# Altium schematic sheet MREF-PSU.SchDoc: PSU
size A4; CompanyName: TRINAMIC; DocumentNumber: 3; SheetNumber: 3; SheetTotal: 5; Author: Indrek Rebane; DrawnBy: Indrek Rebane; Engineer: Indrek Rebane; Organization: Hedgehog OÜ; Address1: Waterloohain 5; Address2: 22769 Hamburg; Address3: Germany; Address4: tmc_info@trinamic.com
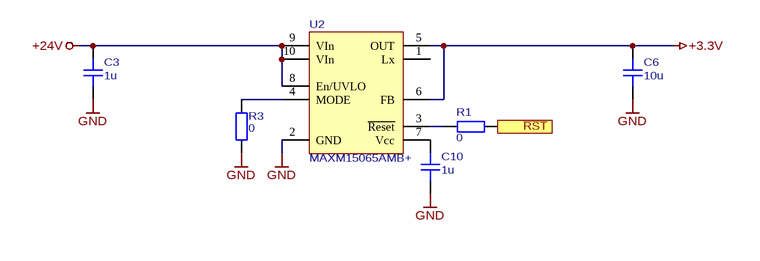
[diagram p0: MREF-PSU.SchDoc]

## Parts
C3  value 1u  [CAPC2012N]  (hidden comment: CAPC)
C6  value 10u  [CAPC2012N]  (hidden comment: CAPC)
C10  value 1u  [CAPC1608N]  (hidden comment: CAPC)
R1  value 0  [RESC1005N]  (hidden comment: RESC)
R3  value 0  [RESC1005N]  (hidden comment: RESC)
U2  Part Number: MAXM15065AMB+  [PSON50P260X165-10N-MFG]  (hidden comment: MAXM1506X)

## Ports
~{RST} (out)

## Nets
+3.3V: C6.2 U2.5(OUT) U2.6(FB)
+24V: C3.2 U2.8(En/UVLO) U2.9(VIn) U2.10(VIn)
GND: C3.1 C6.1 C10.1 R3.2 U2.2(GND)
~{RST}: R1.1 ; port ~{RST}
NetC10_2: C10.2 U2.7(Vcc)
NetR1_2: R1.2 U2.3(~{Reset})
NetR3_1: R3.1 U2.4(MODE)

Not connected (* = marked no-connect by the designer): U2 1(Lx)

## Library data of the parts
C3 = 20079: Ceramic chip capacitor; Manufacturer: Any; Part Number: 1u, 50V, X5R, 0805 (2012 metric) chip capacitor; Id: 20079; Voltage: 50V
C6 = 20166: Ceramic chip capacitor; Manufacturer: Any; Part Number: 10u, 10V, X7R, 0805 (2012 metric) chip capacitor; Id: 20166; Voltage: 10V
C10 = 20005: Ceramic chip capacitor; Manufacturer: Any; Part Number: 1u, 16V, X5R, 0603 (1608 metric) chip capacitor; Id: 20005; Voltage: 16V
R1 R3 = 10052: Chip Resistor; Manufacturer: Any; Part Number: 0, -, -, 0402 (1005 metric) chip resistor; Id: 10052
U2 = 51519: Manufacturer: Maxim Integrated; Id: 51519; Value: 3.3V, 300mA buck PSU module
